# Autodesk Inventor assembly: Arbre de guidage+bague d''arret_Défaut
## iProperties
Shininess: 64.0
Length Units: 11269
Angle Units: 11279
Time Units: 11290
Mass Units: 11283
Length Display Precision: 3
Angle Display Precision: 2
Compacted: True
Created: 2006-11
Part Number: Arbre de guidage+bague d''arret_Défaut
Document SubType Name: Assembly
Designer: profs_sti
Density: 0.0
Volumn: 0.0
Area: 0.0
PropertySet Name: Model Information
Control State: 0
Master: False
Checked Out: False
Author: profs_sti
